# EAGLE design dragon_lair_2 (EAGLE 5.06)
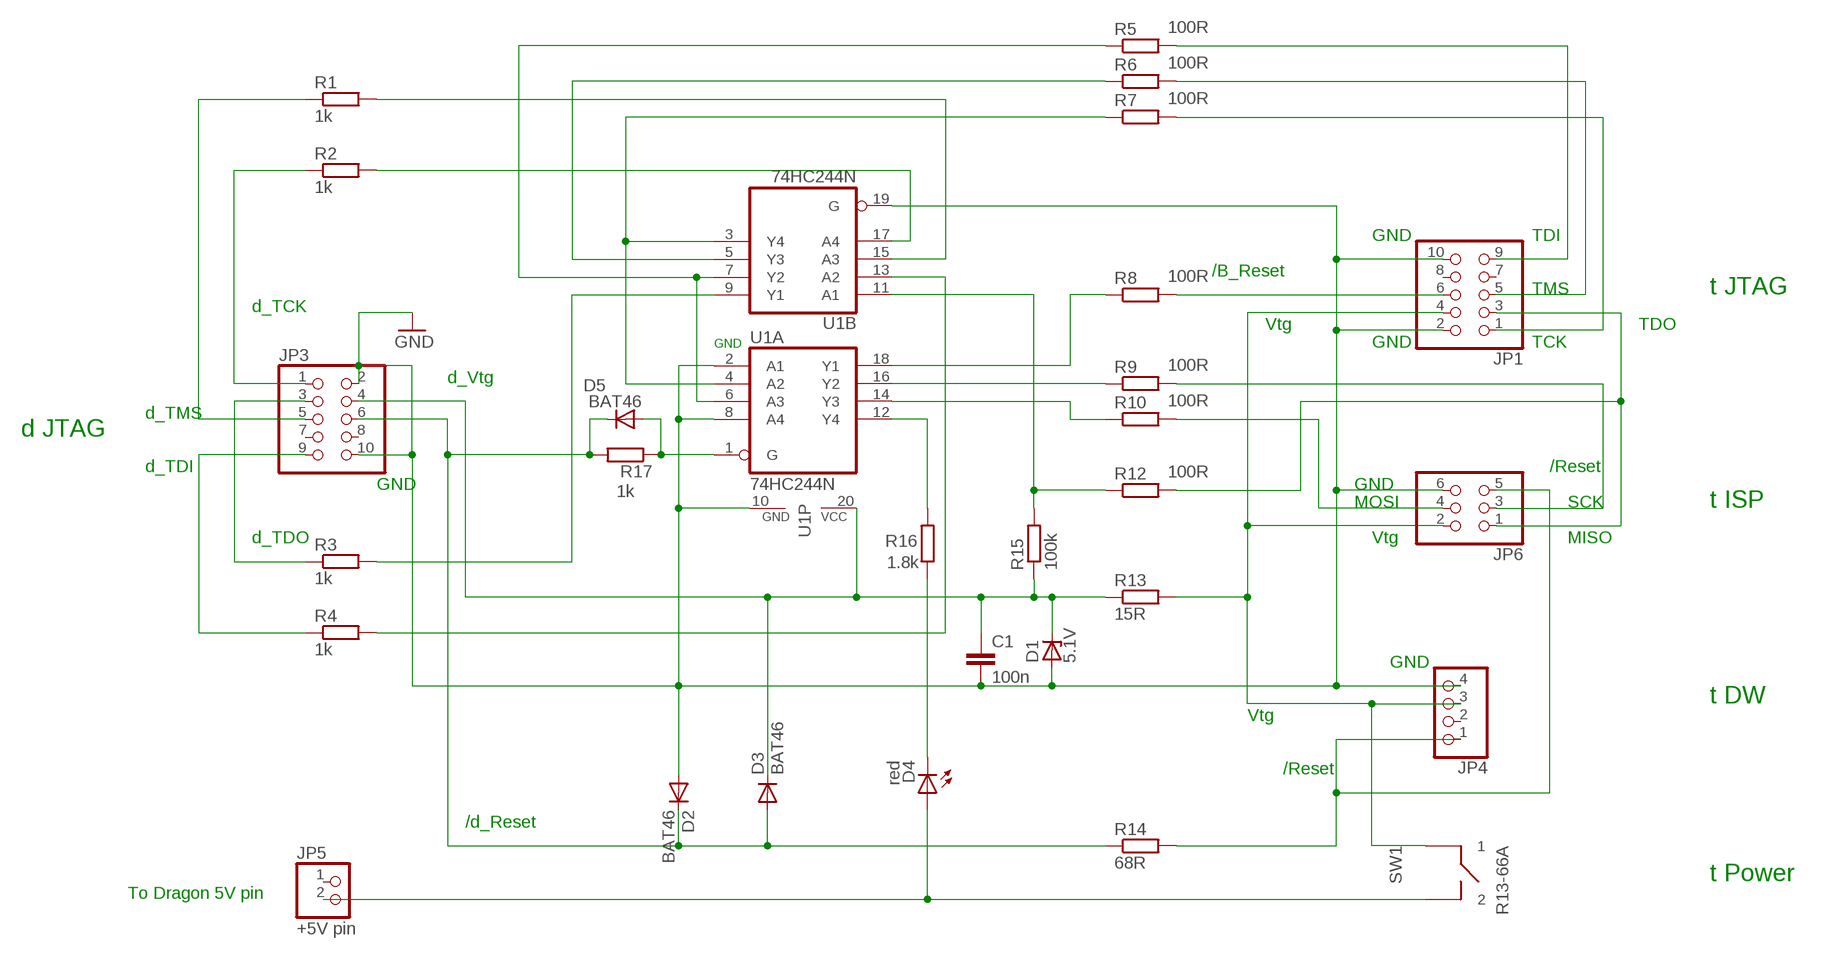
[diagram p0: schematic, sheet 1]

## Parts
C1  100n  C2,5-3  [C2.5-3]
D1  5.1V  ZENER-DIODEZD-5  [ZDIO-5]
D2  BAT46  MBR0520LT  [SOD123]
D3  BAT46  MBR0520LT  [SOD123]
D4  red  LED3MM  [LED3MM]
D5  BAT46  MBR0520LT  [SOD123]
JP1  PINHD-2X5  [2X05]
JP3  PINHD-2X5  [2X05]
JP4  PINHD-1X4  [1X04]
JP5  +5V pin  PINHD-1X2  [1X02]
JP6  PINHD-2X3  [2X03]
R1  1k  R-EU_0204/7  [0204/7]
R2  1k  R-EU_0204/7  [0204/7]
R3  1k  R-EU_0204/7  [0204/7]
R4  1k  R-EU_0204/7  [0204/7]
R5  100R  R-EU_0204/7  [0204/7]
R6  100R  R-EU_0204/7  [0204/7]
R7  100R  R-EU_0204/7  [0204/7]
R8  100R  R-EU_0204/7  [0204/7]
R9  100R  R-EU_0204/7  [0204/7]
R10  100R  R-EU_0204/7  [0204/7]
R12  100R  R-EU_0204/7  [0204/7]
R13  15R  R-EU_0204/7  [0204/7]
R14  68R  R-EU_0204/7  [0204/7]
R15  100k  R-EU_0204/7  [0204/7]
R16  1.8k  R-EU_0204/7  [0204/7]
R17  1k  R-EU_0204/7  [0204/7]
SW1  R13-66A  [R13-66A]
U1  74HC244N  [DIL20]

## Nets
GND [GND]: C1.2 D1.A D2.A JP1.2 JP1.10 JP3.2 JP3.10 JP4.4 JP6.6 U1.2(A:A1) U1.8(A:A4) U1.10(P:GND) U1.19(B:G)
N$1 [+5v]: JP3.1 R2.1
N$2 [+5v]: R5.1 U1.6(A:A3) U1.7(B:Y2)
N$3 [+5v]: JP3.5 R1.1
N$4 [+5v]: R1.2 U1.15(B:A3)
N$5 [+5v]: JP3.3 R3.1
N$6 [+5v]: R3.2 U1.9(B:Y1)
N$7 [+5v]: D5.A R17.1 U1.1(A:G)
N$8 [+5v]: D2.C D3.A D5.C JP3.6 R14.1 R17.2
N$9 [+5v]: JP3.9 R4.1
N$10 [+5v]: R4.2 U1.13(B:A2)
N$11 [+5v]: JP4.1 JP6.5 R14.2
N$12 [+5v]: D4.A JP5.2 SW1.P2
N$13 [+5v]: JP1.4 JP4.3 JP6.2 R13.2 SW1.P1
N$14 [+5v]: C1.1 D1.C D3.C JP3.4 R13.1 R15.1 U1.20(P:VCC)
N$15 [+5v]: D4.K(C) R16.1
N$16 [+5v]: R16.2 U1.12(A:Y4)
N$17 [+5v]: R12.1 R15.2 U1.11(B:A1)
N$18 [+5v]: JP1.9 R5.2
N$19 [+5v]: R6.1 U1.5(B:Y3)
N$20 [+5v]: JP1.5 R6.2
N$21 [+5v]: R7.1 U1.3(B:Y4) U1.4(A:A2)
N$22 [+5v]: JP1.1 R7.2
N$23 [+5v]: R8.1 U1.18(A:Y1)
N$24 [+5v]: JP1.6 R8.2
N$25 [+5v]: R9.1 U1.16(A:Y2)
N$26 [+5v]: JP6.3 R9.2
N$27 [+5v]: R10.1 U1.14(A:Y3)
N$28 [+5v]: JP6.4 R10.2
N$30 [+5v]: JP1.3 JP6.1 R12.2
N$31 [+5v]: R2.2 U1.17(B:A4)
Unconnected: JP1.7 JP1.8 JP3.7 JP3.8 JP4.2 JP5.1

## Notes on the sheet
- GND | TDI
- /B_Reset
- TMS | t JTAG
- d_TCK
- Vtg | TDO
- GND | GND | TCK
- d_Vtg
- d_TMS
- d JTAG
- d_TDI | /Reset
- GND | GND
- MOSI | SCK | t ISP
- d_TDO | Vtg | MISO
- GND
- t DW
- Vtg
- /Reset
- /d_Reset
- t Power
- To Dragon 5V pin

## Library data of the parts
C1 = capacitor-wima:C: CAPACITOR
D1 = diode:ZENER-DIODE: Z-Diode
D2 D3 D5 = diode:MBR0520LT: SCHOTTKY BARRIER RECTIFIER
D4 = led:LED: LED
JP1 JP3 = pinhead:PINHD-2X5: PIN HEADER
JP4 = pinhead:PINHD-1X4: PIN HEADER
JP5 = pinhead:PINHD-1X2: PIN HEADER
JP6 = pinhead:PINHD-2X3: PIN HEADER
R1-R10 R12-R17 = rcl:R-EU_: RESISTOR, European symbol
SW1 = my_switch:R13-66A
U1 = 74xx-eu:74*244: Octal BUFFER and LINE DRIVER, 3-state

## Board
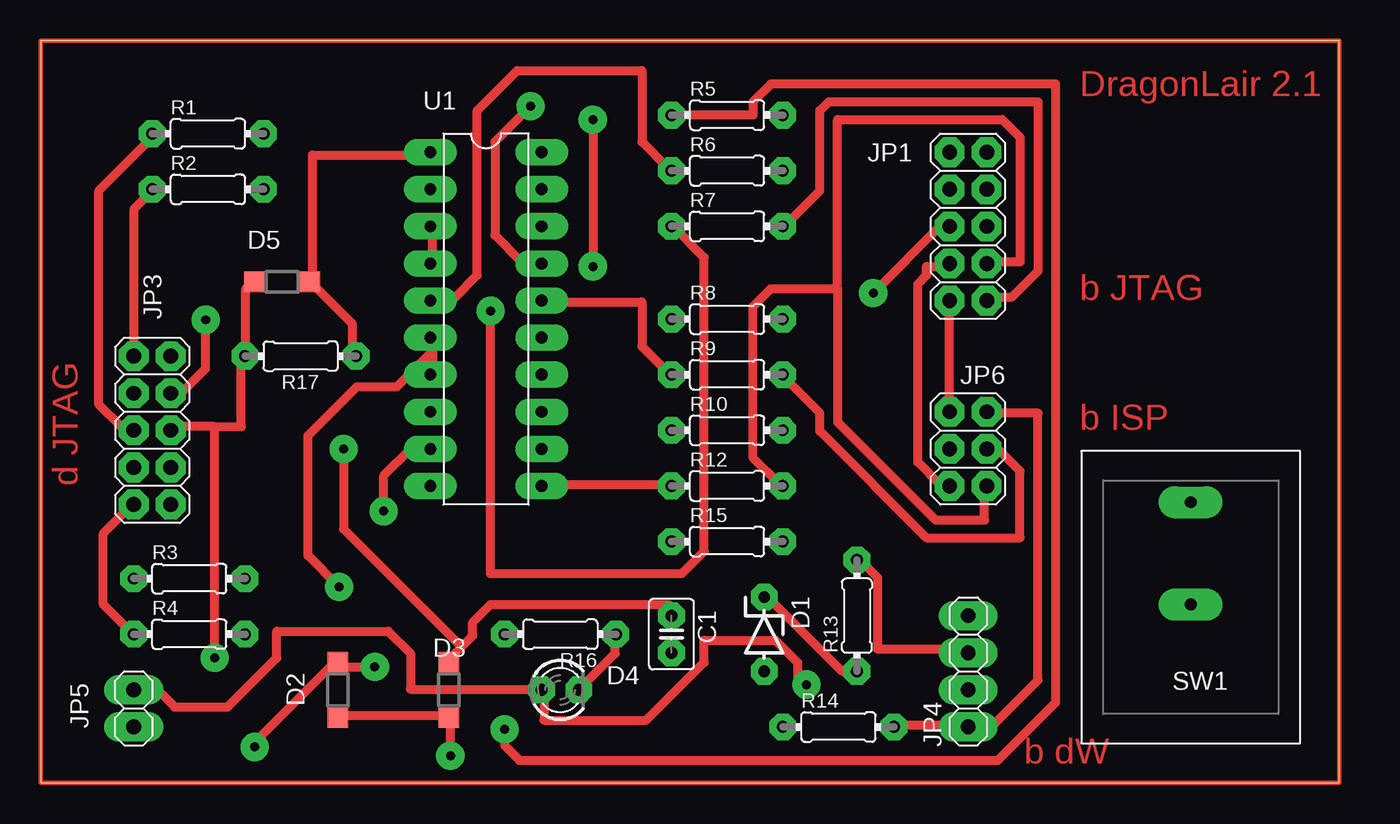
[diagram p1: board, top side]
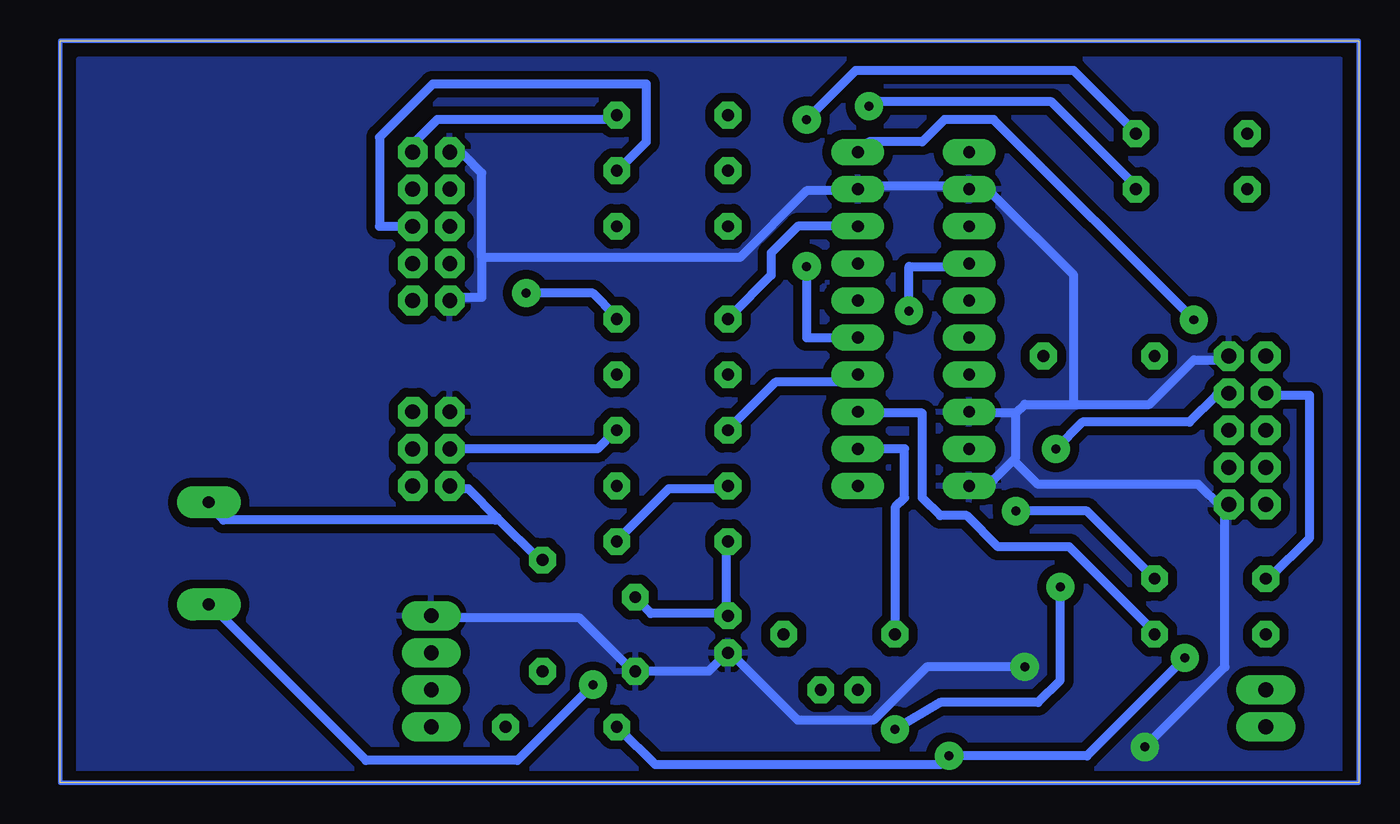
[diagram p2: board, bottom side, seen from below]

Size 88.9 x 50.8 mm. Coordinates in mm from the lower left corner, seen from the top.
Outline: 0,0 88.9,0 88.9,50.8 0,50.8 0,0
Copper layers (1*16): Top 0.035mm / dielectric 1.5mm / Bottom 0.035mm
Design rules "handmade": minimum track width 24mil, minimum drill 24mil, track to track 24mil, track to pad 32mil, pad to pad 32mil, via to via 32mil, smd to smd 32mil, copper to edge 32mil, drill to drill 32mil, minimum pad ring 20mil, minimum via ring 20mil, stop-mask expansion 8mil, vias tented up to drill 0mil, thermal gap 16mil

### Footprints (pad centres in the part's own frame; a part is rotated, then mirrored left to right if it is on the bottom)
C2.5-3 = drill 0.813 pad 1.6 octagon: 1 -1.27,0; 2 1.27,0
ZDIO-5 = drill 0.813 octagon: A 2.54,0; C -2.54,0
SOD123 = smd 1.4 x 1.4: A 1.9,0; C -1.9,0
LED3MM = drill 0.813 octagon: A -1.27,0; K 1.27,0
2X05 = drill 1.016 octagon: 1 -5.08,-1.27; 2 -5.08,1.27; 3 -2.54,-1.27; 4 -2.54,1.27; 5 0,-1.27; 6 0,1.27; 7 2.54,-1.27; 8 2.54,1.27; 9 5.08,-1.27; 10 5.08,1.27
1X04 = drill 1.016 long: 1 -3.81,0; 2 -1.27,0; 3 1.27,0; 4 3.81,0
1X02 = drill 1.016 long: 1 -1.27,0; 2 1.27,0
2X03 = drill 1.016 octagon: 1 -2.54,-1.27; 2 -2.54,1.27; 3 0,-1.27; 4 0,1.27; 5 2.54,-1.27; 6 2.54,1.27
0204/7 = drill 0.813 octagon: 1 -3.81,0; 2 3.81,0
R13-66A = drill 0.8 pad 2.184 long: P1 -6.5,0; P2 0.5,0
DIL20 = drill 0.813 long: 1 -11.43,-3.81; 2 -8.89,-3.81; 3 -6.35,-3.81; 4 -3.81,-3.81; 5 -1.27,-3.81; 6 1.27,-3.81; 7 3.81,-3.81; 8 6.35,-3.81; 9 8.89,-3.81; 10 11.43,-3.81; 11 11.43,3.81; 12 8.89,3.81; 13 6.35,3.81; 14 3.81,3.81; 15 1.27,3.81; 16 -1.27,3.81; 17 -3.81,3.81; 18 -6.35,3.81; 19 -8.89,3.81; 20 -11.43,3.81

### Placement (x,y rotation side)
C1  43.18,10.16 270 top
D1  49.53,10.16 270 top
D2  20.32,6.35 90 top
D3  27.94,6.35 270 top
D4  35.56,6.35 0 top
D5  16.51,34.29 0 top
JP1  63.5,38.1 90 top
JP3  7.62,24.13 270 top
JP4  63.5,7.62 90 top
JP5  6.35,5.08 90 top
JP6  63.5,22.86 90 top
R1  11.43,44.45 0 top
R2  11.43,40.64 0 top
R3  10.16,13.97 0 top
R4  10.16,10.16 0 top
R5  46.99,45.72 0 top
R6  46.99,41.91 0 top
R7  46.99,38.1 0 top
R8  46.99,31.75 0 top
R9  46.99,27.94 0 top
R10  46.99,24.13 0 top
R12  46.99,20.32 0 top
R13  55.88,11.43 90 top
R14  54.61,3.81 0 top
R15  46.99,16.51 0 top
R16  35.56,10.16 180 top
R17  17.78,29.21 180 top
SW1  78.74,12.7 270 top
U1  30.48,31.75 270 top
U$1  [PASSMARK]  not placed on the board
U$2  [PASSMARK]  not placed on the board

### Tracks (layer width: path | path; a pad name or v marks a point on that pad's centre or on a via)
GND  (via drill 0.61 pad 1.93)
  Top 0.61: v14.63,2.44 14.63,2.74 20.12,8.23 D2.A 20.12,7.92 v22.86,7.92 | JP6.6 62.18,25.6 62.18,32.92 JP1.2
  Bottom 0.61: JP4.4 63.4,11.28 53.34,11.28 49.68,7.62 D1.A 44.5,7.62 43.28,8.84 C1.2 42.98,8.84 38.41,4.27 33.22,4.27 29.57,7.92 v22.86,7.92 | v14.63,2.44 9.14,7.92 9.14,18.9 JP3.10 9.45,18.9 10.97,20.42 21.95,20.42 23.62,22.1 | 60.05,35.97 60.05,33.22 62.18,33.22 JP1.2 | 60.05,35.97 60.05,41.76 61.27,42.98 62.18,42.98 JP1.10 | 23.62,22.1 23.47,22.25 23.47,25.3 | 23.62,22.1 24.99,20.73 26.21,20.73 26.52,20.42 U1.10 | 23.47,25.3 26.52,25.3 U1.8 | 19.51,25.91 22.86,25.91 23.47,25.3 | 19.51,25.91 14.33,25.91 11.28,28.96 9.14,28.96 JP3.2 | 19.51,25.91 19.51,34.75 24.99,40.23 26.21,40.23 26.52,40.54 U1.2 26.82,40.84 34.14,40.84 U1.19 34.44,40.54 37.8,40.54 42.37,35.97 60.05,35.97
  pour Bottom: 1.27,49.53 87.63,49.53 87.63,0 1.27,0
N$1
  Top 0.61: R2.1 7.62,40.54 6.4,39.32 6.4,29.26 JP3.1
N$2  (via drill 0.61 pad 1.93)
  Top 0.61: 26.82,29.57 26.82,30.48 U1.6 | 26.82,29.57 26.82,28.04 U1.7 | v20.42,13.41 18.29,15.54 18.29,23.77 21.64,27.13 24.38,27.13 26.82,29.57 | R5.1 48.77,45.72 48.77,46.63 49.99,47.85 69.49,47.85 69.49,5.49 65.53,1.52 32.77,1.52 31.75,2.54 v31.75,3.66
  Bottom 0.61: v31.75,3.66 28.65,5.49 21.95,5.49 20.42,7.01 v20.42,13.41
N$3
  Top 0.61: 7.62,44.2 3.96,40.54 3.96,25.91 5.49,24.38 6.1,24.38 JP3.5
  Top 0.813: 7.62,44.2 R1.1
N$4  (via drill 0.61 pad 1.93)
  Top 0.61: v37.8,45.41 v37.8,35.36
  Bottom 0.61: v37.8,45.41 34.44,48.77 19.51,48.77 15.24,44.5 R1.2 | v37.8,35.36 37.8,30.48 U1.15
N$5
  Bottom 0.61: R3.1 6.1,14.02 3.35,16.76 3.35,26.52 6.1,26.52 JP3.3
N$6  (via drill 0.61 pad 1.93)
  Top 0.61: v23.47,18.59 23.47,21.03 25.3,22.86 U1.9
  Bottom 0.61: v23.47,18.59 18.59,18.59 R3.2
N$7
  Top 0.61: R17.1 21.34,29.26 21.34,31.39 18.59,34.14 D5.A 18.59,34.44 18.59,42.98 26.52,42.98 U1.1
N$8  (via drill 0.61 pad 1.93)
  Top 0.61: D5.C 14.33,34.14 14.02,33.83 14.02,29.26 R17.2 13.72,28.96 13.72,24.38 11.89,24.38 | 11.89,24.38 9.14,24.38 JP3.6 | D2.C 20.42,4.57 27.74,4.57 D3.A 28.04,4.27 v28.04,1.83 | v11.89,8.53 11.89,24.38
  Bottom 0.61: R14.1 50.6,3.66 48.16,1.22 28.65,1.22 v28.04,1.83 18.59,1.83 v11.89,8.53
N$9
  Top 0.61: R4.1 6.1,10.36 4.27,12.19 4.27,17.07 6.1,18.9 JP3.9
N$10
  Bottom 0.61: R4.2 14.02,10.36 19.81,16.15 24.69,16.15 26.82,18.29 28.65,18.29 29.87,19.51 29.87,25.3 34.14,25.3 U1.13
N$11
  Top 0.61: R14.2 58.52,3.96 63.4,3.96 JP4.1 63.7,3.96 65.23,3.96 68.28,7.01 68.28,25.3 64.92,25.3 JP6.5
N$12  (via drill 0.61 pad 1.93)
  Top 0.61: JP5.2 6.4,6.1 8.23,6.1 9.14,5.18 12.8,5.18 16.15,8.53 16.15,10.36 23.77,10.36 25.3,8.84 25.3,6.4 34.14,6.4 D4.A 34.44,6.1 34.44,4.27 41.45,4.27 45.41,8.23 45.41,9.75 50.29,9.75 51.82,8.23 51.82,7.32 v52.43,6.71
  Bottom 0.61: v52.43,6.71 57.61,1.52 67.97,1.52 78.64,12.19 SW1.P2
N$13
  Top 0.61: JP1.4 62.18,35.36 60.66,35.36 60.66,34.75 60.05,34.14 60.05,21.95 61.57,20.42 62.18,20.42 JP6.2 | JP4.3 63.4,9.14 57.3,9.14 57.3,14.02 56.08,15.24 R13.2
  Bottom 0.61: 58.98,18.14 60.96,20.12 62.18,20.12 JP6.2 | 58.98,18.14 56.08,15.24 R13.2 | SW1.P1 78.64,18.9 77.72,17.98 59.13,17.98 58.98,18.14
N$14  (via drill 0.61 pad 1.93)
  Top 0.61: 28.8,9.3 29.57,10.06 29.57,10.97 30.79,12.19 42.98,12.19 42.98,11.58 C1.1 | 28.8,9.3 28.04,8.53 D3.C | R13.1 54.86,7.62 49.68,12.8 D1.C | v11.28,31.7 11.28,28.35 9.75,26.82 9.14,26.82 JP3.4 | v20.73,22.86 20.73,17.37 28.8,9.3
  Bottom 0.61: D1.C 49.38,12.5 48.46,11.58 43.28,11.58 C1.1 43.28,11.89 43.28,16.46 R15.1 | v11.28,31.7 24.99,45.41 28.35,45.41 29.87,43.89 33.53,43.89 34.14,43.28 U1.20 | v20.73,22.86 18.9,24.69 11.58,24.69 9.75,26.52 9.14,26.52 JP3.4
N$15
  Top 0.61: D4.K 39.32,8.84 39.32,10.06 R16.1
N$16
  Bottom 0.61: R16.2 31.7,10.36 31.7,18.9 31.09,19.51 31.09,22.86 U1.12
N$17
  Top 0.61: U1.11 34.44,20.42 42.98,20.42 R12.1
  Bottom 0.61: R15.2 50.6,16.76 47.24,20.12 43.28,20.12 R12.1
N$18
  Bottom 0.61: R5.2 50.9,45.72 51.21,45.41 63.09,45.41 64.62,43.89 64.62,43.28 JP1.9
N$19
  Top 0.61: U1.5 26.82,33.22 28.35,33.22 29.87,34.75 29.87,46.02 32.61,48.77 41.15,48.77 41.15,43.89 42.98,42.06 R6.1
N$20
  Bottom 0.61: R6.2 50.6,42.06 48.77,43.89 48.77,47.85 63.4,47.85 67.06,44.2 67.06,38.1 JP1.5
N$21  (via drill 0.61 pad 1.93)
  Top 0.61: U1.4 26.82,35.66 26.82,38.1 U1.3 | v30.79,32.31 30.79,14.33 43.89,14.33 45.41,15.85 45.41,35.97 43.28,38.1 R7.1
  Bottom 0.61: v30.79,32.31 30.79,35.36 26.82,35.36 U1.4
N$22
  Top 0.61: R7.2 50.9,38.1 53.34,40.54 53.34,46.02 53.95,46.63 68.28,46.63 68.28,35.05 66.45,33.22 64.92,33.22 JP1.1
N$23
  Bottom 0.61: R8.1 42.98,32 40.23,34.75 40.23,36.27 38.41,38.1 U1.18
N$24  (via drill 0.61 pad 1.93)
  Top 0.61: v57,33.53 61.57,38.1 JP1.6
  Bottom 0.61: v57,33.53 52.43,33.53 50.9,32 R8.2
N$25
  Top 0.61: U1.16 34.44,32.92 41.15,32.92 41.15,29.87 42.98,28.04 R9.1
N$26
  Top 0.61: R9.2 50.9,27.74 53.34,25.3 53.34,24.08 60.66,16.76 67.06,16.76 67.06,21.34 65.53,22.86 JP6.3
N$27
  Bottom 0.61: U1.14 34.44,27.74 34.75,27.43 39.93,27.43 42.98,24.38 R10.1
N$28
  Bottom 0.61: R10.2 50.9,24.08 52.12,22.86 JP6.4
N$29
  Top 0.305: 0,50.8 88.9,50.8 88.9,0 0,0 0,50.8
N$30
  Top 0.61: 54.56,33.83 49.99,33.83 48.77,32.61 48.77,22.25 50.6,20.42 R12.2 | 54.56,33.83 54.56,24.69 61.27,17.98 64.62,17.98 64.62,20.12 JP6.1 | 54.56,33.83 54.56,45.41 65.84,45.41 67.06,44.2 67.06,35.66 64.92,35.66 JP1.3
N$31  (via drill 0.61 pad 1.93)
  Top 0.61: v33.53,46.33 31.09,43.89 31.09,37.49 32.92,35.66 34.14,35.66 U1.17
  Bottom 0.61: v33.53,46.33 33.22,46.63 21.03,46.63 15.24,40.84 R2.2
N$32
  Bottom 0.305: 0,50.8 88.9,50.8 88.9,0 0,0 0,50.8

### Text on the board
Top: DragonLair 2.1 | b JTAG | b ISP | d JTAG | b dW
